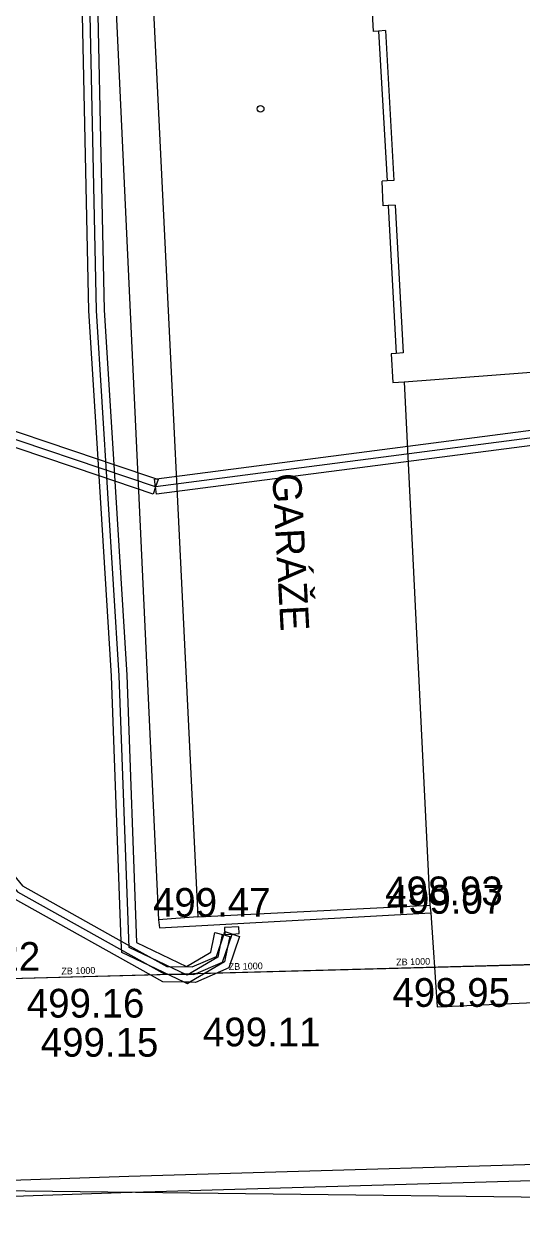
# Model space of a CAD drawing. Extents: x -669642 to -669119, y -1131006 to -1130466.
# Drawn here: x -669617.17 to -669604.18, y -1130597.5 to -1130566.14 of the extents above; entities that cross this region are included whole.
import ezdxf

# ---------------------------------------------------------------- set-up
doc = ezdxf.new("R2010")
doc.units = 0
for name, color, linetype in [('G_Bod_tecka', 7, 'Continuous'), ('G_Bod_vyska', 7, 'Continuous'), ('G_Budovy-znacky', 7, 'Continuous'), ('G_Budovy_Objekty', 7, 'Continuous'), ('G_Plochy_zpevnene', 7, 'Continuous'), ('G_Ploty', 7, 'Continuous'), ('G_Popisy_objektu', 7, 'Continuous'), ('G_Site-Rozvadece', 7, 'Continuous'), ('G_Z_CHRANICKA-TEPLOVOD_kotovane', 7, 'Continuous'), ('G_Z_CHRANICKA-TEPLOVOD_zahozene', 7, 'Continuous'), ('G_Z_ELsilove_podz_kotovane', 7, 'Continuous'), ('G_Z_KANAL_podz_kotovane', 7, 'Continuous'), ('Vrstva 12', 7, 'Continuous'), ('Vrstva 3', 7, 'Continuous')]:
    doc.layers.add(name, color=color, linetype=linetype)

msp = doc.modelspace()

# ---------------------------------------------------------------- linework, layer by layer
at = {"layer": 'G_Bod_tecka'}
for p, q in [((-669606.58, -1130589.13), (-669606.58, -1130589.13)), ((-669612.64, -1130589.43), (-669612.64, -1130589.43)), ((-669606.52, -1130589.35), (-669606.52, -1130589.35)), ((-669606.39, -1130591.78), (-669606.39, -1130591.78)), ((-669616.06, -1130592.06), (-669616.06, -1130592.06)), ((-669611.54, -1130592.81), (-669611.54, -1130592.81)), ((-669615.71, -1130593.08), (-669615.71, -1130593.08))]:
    msp.add_line(p, q, dxfattribs=at)
at = {"layer": 'G_Budovy-znacky'}
msp.add_circle((-669611, -1130568.35), 0.0875, dxfattribs=at)
at = {"layer": 'G_Budovy_Objekty'}
for p, q in [((-669613.91, -1130563.51), (-669612.64, -1130589.43)), ((-669608.05, -1130566.33), (-669608.09, -1130565.69)), ((-669607.92, -1130566.32), (-669608.05, -1130566.33)), ((-669607.74, -1130566.31), (-669607.92, -1130566.32)), ((-669607.92, -1130566.32), (-669607.7, -1130570.23)), ((-669607.74, -1130566.31), (-669607.52, -1130570.22)), ((-669607.7, -1130570.23), (-669607.83, -1130570.24)), ((-669607.8, -1130570.88), (-669607.83, -1130570.24)), ((-669607.52, -1130570.22), (-669607.7, -1130570.23)), ((-669607.67, -1130570.87), (-669607.8, -1130570.88)), ((-669607.49, -1130570.86), (-669607.67, -1130570.87)), ((-669607.67, -1130570.87), (-669607.46, -1130574.73)), ((-669607.49, -1130570.86), (-669607.28, -1130574.72)), ((-669607.46, -1130574.73), (-669607.59, -1130574.74)), ((-669607.59, -1130574.74), (-669607.55, -1130575.49)), ((-669607.28, -1130574.72), (-669607.46, -1130574.73)), ((-669607.25, -1130575.47), (-669601.62, -1130575.04)), ((-669607.55, -1130575.49), (-669607.25, -1130575.47)), ((-669612.64, -1130589.43), (-669606.58, -1130589.13)), ((-669606.58, -1130589.13), (-669606.56, -1130589.33)), ((-669606.56, -1130589.33), (-669606.39, -1130591.78)), ((-669606.39, -1130591.78), (-669595.41, -1130591.28))]:
    msp.add_line(p, q, dxfattribs=at)
msp.add_lwpolyline([(-669607.25, -1130575.47), (-669606.58, -1130589.13)], dxfattribs=at)
at = {"layer": 'G_Plochy_zpevnene'}
msp.add_line((-669614.89, -1130563.29), (-669613.66, -1130589.51), dxfattribs=at)
at = {"layer": 'G_Ploty'}
msp.add_line((-669613.64, -1130589.72), (-669606.56, -1130589.33), dxfattribs=at)
msp.add_lwpolyline([(-669612.64, -1130589.43), (-669613.66, -1130589.51), (-669613.64, -1130589.72)], dxfattribs=at)
at = {"layer": 'G_Site-Rozvadece'}
msp.add_lwpolyline([(-669611.93, -1130589.89), (-669611.74, -1130589.88), (-669611.56, -1130589.87), (-669611.57, -1130589.69), (-669611.94, -1130589.71), (-669611.93, -1130589.89)], dxfattribs=at)
at = {"layer": 'G_Z_CHRANICKA-TEPLOVOD_kotovane'}
for points in [[(-669530.86, -1130536.09), (-669531.69, -1130536.11), (-669538.05, -1130536.01), (-669551.6, -1130535.98), (-669556.47, -1130536.1), (-669556.55, -1130536.06), (-669560.64, -1130536.09), (-669574.53, -1130536.2), (-669574.67, -1130536.36), (-669574.72, -1130541.62), (-669574.88, -1130541.76), (-669582.24, -1130541.63), (-669583.55, -1130541.58), (-669583.7, -1130541.72), (-669584.58, -1130558.61), (-669585.58, -1130575.76), (-669585.93, -1130595.21), (-669586.1, -1130595.37), (-669614.44, -1130596.21), (-669640.046, -1130597.079)], [(-669640.046, -1130597.497), (-669614.65, -1130596.62), (-669585.75, -1130595.78), (-669585.6, -1130595.63), (-669585.16, -1130575.89), (-669584.28, -1130558.61), (-669583.35, -1130542.15), (-669583.19, -1130542.01), (-669581.88, -1130542.11), (-669574.53, -1130542.49), (-669574.36, -1130542.36), (-669574.15, -1130537.08), (-669574.02, -1130536.91), (-669560.19, -1130536.48), (-669556.56, -1130536.39), (-669556.35, -1130536.38), (-669551.53, -1130536.3), (-669538.03, -1130536.37), (-669531.82, -1130536.43), (-669530.95, -1130536.44)], [(-669615.33, -1130561.836), (-669615.08, -1130573.602), (-669614.831, -1130577.632), (-669614.804, -1130578.063), (-669614.49, -1130583.13), (-669614.235, -1130590.102), (-669612.93, -1130590.724), (-669612.298, -1130590.355), (-669612.215, -1130589.929), (-669612.193, -1130589.844), (-669611.959, -1130589.902), (-669611.805, -1130589.941), (-669611.824, -1130590.016), (-669611.941, -1130590.609), (-669612.846, -1130591.139), (-669612.91, -1130591.176), (-669612.993, -1130591.137), (-669614.625, -1130590.358), (-669614.636, -1130590.065), (-669614.89, -1130583.15), (-669615.213, -1130577.925), (-669615.24, -1130577.494), (-669615.48, -1130573.618), (-669615.73, -1130561.844)]]:
    msp.add_lwpolyline(points, dxfattribs=at)
for points in [[(-669620.251, -1130576.024), (-669618.648, -1130576.346), (-669615.24, -1130577.494), (-669614.831, -1130577.632), (-669613.72, -1130578.006), (-669613.676, -1130578.02), (-669613.74, -1130578.21), (-669613.804, -1130578.4), (-669614.804, -1130578.063), (-669615.213, -1130577.925), (-669618.752, -1130576.734), (-669619.224, -1130576.639), (-669620.279, -1130576.426), (-669620.33, -1130576.416), (-669620.29, -1130576.22), (-669620.29, -1130576.22), (-669620.29, -1130576.22)], [(-669613.72, -1130578.006), (-669600.596, -1130576.302), (-669600.57, -1130576.501), (-669600.544, -1130576.698), (-669600.551, -1130576.699), (-669613.714, -1130578.408), (-669613.74, -1130578.21), (-669613.766, -1130578.012)], [(-669621.109, -1130584.098), (-669621.044, -1130584.162), (-669620.991, -1130584.215), (-669620.082, -1130585.115), (-669617.209, -1130588.624), (-669614.636, -1130590.065), (-669613.447, -1130590.731), (-669612.781, -1130590.739), (-669612.151, -1130590.462), (-669611.959, -1130589.902), (-669611.929, -1130589.815), (-669611.551, -1130589.945), (-669611.829, -1130590.758), (-669612.699, -1130591.141), (-669612.846, -1130591.139), (-669612.993, -1130591.137), (-669613.553, -1130591.129), (-669617.471, -1130588.936), (-669620.378, -1130585.385), (-669621.391, -1130584.382), (-669621.25, -1130584.24), (-669621.25, -1130584.24)]]:
    msp.add_lwpolyline(points, close=True, dxfattribs=at)
at = {"layer": 'G_Z_CHRANICKA-TEPLOVOD_zahozene'}
msp.add_line((-669575.13, -1130597.1), (-669640.046, -1130596.308), dxfattribs=at)
at = {"layer": 'G_Z_ELsilove_podz_kotovane'}
for points in [[(-669611.999, -1130589.892), (-669612.119, -1130590.482), (-669612.92, -1130590.95), (-669614.43, -1130590.23), (-669614.69, -1130583.14), (-669615.28, -1130573.61), (-669615.53, -1130561.84), (-669615.65, -1130554.34), (-669614.36, -1130554.22)], [(-669589.9, -1130574.36), (-669589.91, -1130575.05), (-669590.77, -1130575.55), (-669592.25, -1130575.95), (-669596.1, -1130576.18), (-669600.57, -1130576.5), (-669613.74, -1130578.21), (-669618.7, -1130576.54), (-669619.719, -1130576.335), (-669619.951, -1130576.205), (-669620.306, -1130576.121), (-669621.026, -1130576.161), (-669621.19, -1130576.27), (-669621.014, -1130576.361), (-669620.323, -1130576.322), (-669619.997, -1130576.4), (-669619.18, -1130576.9), (-669619.63, -1130581.88), (-669621.135, -1130584.073), (-669621.248, -1130583.961), (-669621.352, -1130583.685), (-669621.37, -1130583.382)], [(-669621.57, -1130583.39), (-669621.55, -1130583.729), (-669621.421, -1130584.071), (-669620.23, -1130585.25), (-669617.34, -1130588.78), (-669613.5, -1130590.93), (-669612.74, -1130590.94), (-669611.99, -1130590.61), (-669611.74, -1130589.88)]]:
    msp.add_lwpolyline(points, dxfattribs=at)
at = {"layer": 'G_Z_KANAL_podz_kotovane'}
msp.add_line((-669640.046, -1130591.644), (-669575.91, -1130589.92), dxfattribs=at)
at = {"layer": 'Vrstva 12'}
msp.add_line((-669640.046, -1130591.649), (-669575.912, -1130589.924), dxfattribs=at)

# ---------------------------------------------------------------- texts
at = {"layer": 'G_Bod_vyska'}
for s, p in [('498.93', (-669607.748, -1130589.13)), ('499.07', (-669607.71, -1130589.35)), ('499.47', (-669613.808, -1130589.43)), ('499.22', (-669619.818, -1130590.84)), ('498.95', (-669607.558, -1130591.78)), ('499.16', (-669617.1, -1130592.06)), ('499.11', (-669612.504, -1130592.81)), ('499.15', (-669616.736, -1130593.08))]:
    msp.add_text(s, height=0.75, dxfattribs=at).set_placement(p)
at = {"layer": 'G_Popisy_objektu'}
msp.add_text('GARÁŽE', height=0.75, rotation=273.061, dxfattribs=at).set_placement((-669610.695, -1130577.874))
at = {"layer": 'Vrstva 3'}
for p in [(-669607.46, -1130590.702), (-669616.196, -1130590.937), (-669611.829, -1130590.82)]:
    msp.add_text('ZB 1000', height=0.1755, rotation=1.5347, dxfattribs=at).set_placement(p)

doc.saveas('drawing.dxf')
